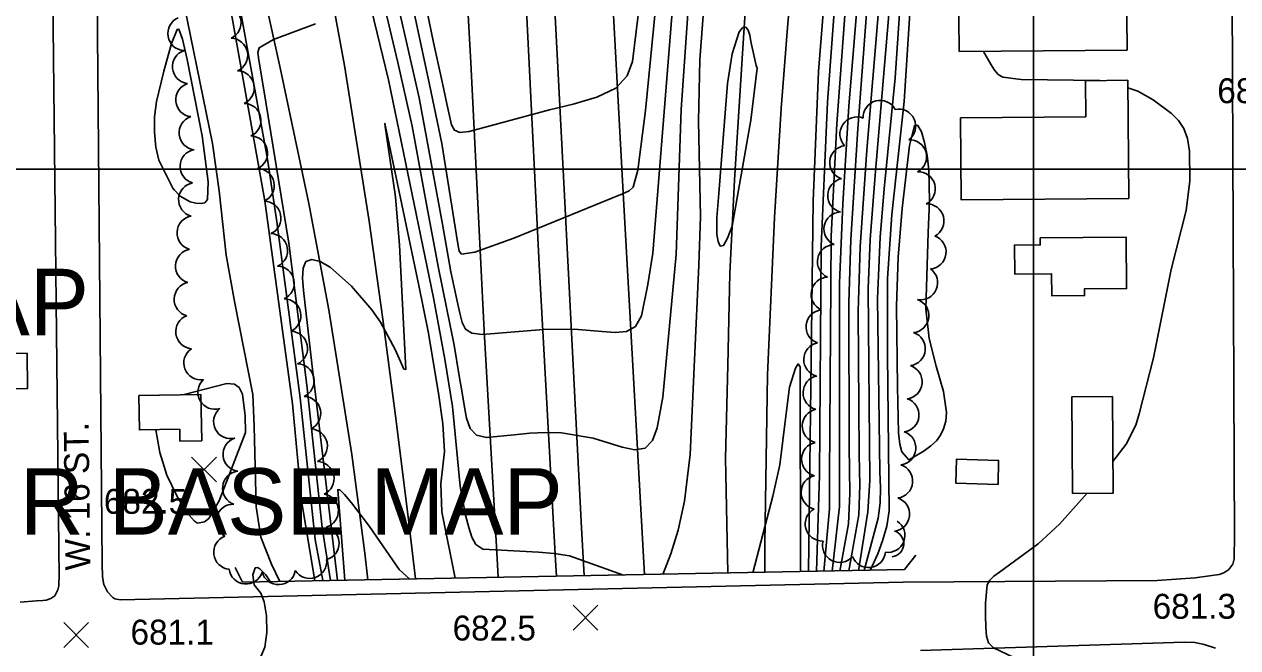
# Model space of a CAD drawing. Extents: x 79600 to 91800, y 75600 to 84400.
# Drawn here: x 86092 to 86823, y 78712 to 79087 of the extents above; entities that cross this region are included whole.
import ezdxf

# ---------------------------------------------------------------- set-up
doc = ezdxf.new("R2010")
doc.units = 0
for name, color, linetype in [('080-085$0$TI_BORDER', 7, 'Continuous'), ('080-085$0$TI_ORTHO_BM', 7, 'Continuous'), ('080-085$0$TI_ORTHO_CBM', 7, 'Continuous'), ('080-090$0$BLDG', 7, 'Continuous'), ('080-090$0$BRIDGE', 7, 'Continuous'), ('080-090$0$GRID', 7, 'Continuous'), ('080-090$0$INDEX', 7, 'Continuous'), ('080-090$0$INTER', 7, 'Continuous'), ('080-090$0$INTERSTATE', 7, 'Continuous'), ('080-090$0$ROAD', 7, 'Continuous'), ('080-090$0$ROAD-NAME', 7, 'Continuous'), ('080-090$0$SPOTMARK', 7, 'Continuous'), ('080-090$0$SPOTS', 7, 'Continuous'), ('080-090$0$TREES', 7, 'Continuous')]:
    doc.layers.add(name, color=color, linetype=linetype)

# ---------------------------------------------------------------- blocks, each defined once
blk = doc.blocks.new('080-090$0$SPOTS')
at = {"layer": '080-090$0$SPOTMARK'}
for p, q in [((-0.5, -0.5), (0.5, 0.5)), ((-0.5, 0.5), (0.5, -0.5))]:
    blk.add_line(p, q, dxfattribs=at)

msp = doc.modelspace()

# ---------------------------------------------------------------- linework, layer by layer
at = {"layer": '080-085$0$TI_BORDER'}
msp.add_lwpolyline([(79700, 80300), (86700, 80300), (86700, 75700), (79700, 75700)], close=True, dxfattribs=at)
at = {"layer": '080-090$0$BLDG'}
for points in [[(86655.25, 79070.71), (86756.42, 79071.59), (86756.07, 79112.06), (86654.89, 79111.18)], [(86731.56, 79031.43), (86731.37, 79053.21), (86756.8, 79053.43), (86757.42, 78982.31), (86656.59, 78981.44), (86656.16, 79030.78)], [(86704.1, 78958.66), (86704.13, 78954.42), (86688.63, 78954.28), (86688.79, 78936.8), (86710.99, 78936.99), (86711.11, 78923.76), (86730.79, 78923.93), (86730.75, 78927.89), (86756.12, 78928.11), (86755.85, 78959.11)], [(86094.11, 78889.17), (86057.05, 78888.61), (86057.37, 78867.46), (86094.43, 78868.02)], [(86161.4, 78863.73), (86161.71, 78843.04), (86186.07, 78843.41), (86186.17, 78836.37), (86199.23, 78836.57), (86198.81, 78864.29)], [(86747.6, 78863.14), (86748.1, 78805.05), (86723.6, 78804.83), (86723.09, 78862.93)], [(86678.72, 78810.25), (86653.33, 78810.91), (86653.7, 78825.37), (86679.1, 78824.71)]]:
    msp.add_lwpolyline(points, close=True, dxfattribs=at)
at = {"layer": '080-090$0$BRIDGE'}
for p, q in [((86622.49, 78759.11), (86629.26, 78767.59)), ((86219.38, 78760.18), (86223.82, 78751.39)), ((86223.82, 78751.39), (86622.49, 78759.11))]:
    msp.add_line(p, q, dxfattribs=at)
at = {"layer": '080-090$0$GRID'}
msp.add_line((90000, 79000), (85000, 79000), dxfattribs=at)
at = {"layer": '080-090$0$INDEX'}
for points in [[(86794.84, 80000), (86783.11, 79983.55), (86767.05, 79957.92), (86758.01, 79940.3), (86743.03, 79904.75), (86719.25, 79841.72), (86707.01, 79806.04), (86679.46, 79703.71), (86668.02, 79658.6), (86660.02, 79622.49), (86647.85, 79558.56), (86633.32, 79464.99), (86610.07, 79282.52), (86599.03, 79207.39), (86591.82, 79149.83), (86587.83, 79111.6), (86581.57, 79027.31), (86578.33, 78959.69), (86577.33, 78815.09), (86577.23, 78795.59), (86573.92, 78757.92)], [(86800.04, 79977.16), (86787.89, 79956.36), (86780.56, 79938.68), (86749.38, 79836.84), (86697.53, 79644.09), (86690.23, 79616.74), (86680.01, 79569.49), (86660.4, 79437.95), (86654.03, 79389.47), (86649.19, 79341.29), (86646.22, 79282.72), (86644.79, 79263.44), (86630.75, 79187.68), (86624.79, 79150.58), (86621.37, 79123.29), (86616.84, 79054.9), (86610.12, 78988.14), (86607.68, 78959.03), (86606.12, 78922.22), (86607.62, 78817.75), (86607.87, 78808.44), (86607.67, 78799.18), (86606.63, 78790.02), (86598.08, 78758.37)], [(86246.21, 78751.85), (86241.19, 78762.32), (86234.9, 78778.52), (86232.13, 78796.81), (86230.81, 78845.4), (86230.04, 78864.39), (86219.18, 78919.23), (86213.99, 78948.14), (86209.79, 78986.84), (86205.66, 79015.43), (86184.94, 79117.68), (86169.63, 79202.98), (86155.24, 79295.88), (86134.2, 79408.83), (86127.12, 79446.68), (86118.5, 79483.87), (86106.7, 79530.75)], [(86267.44, 78752.25), (86259.35, 78800.5), (86253.88, 78858.84), (86237.2, 78980.86), (86199.89, 79190.16)], [(86296.31, 79191.91), (86330.19, 79042.93), (86344.29, 78966.77), (86349.32, 78938.16), (86351.25, 78929), (86353.14, 78920.53), (86354.76, 78913.26), (86356.12, 78907.6), (86358.11, 78903.61), (86361.86, 78901.25), (86368.14, 78900.43), (86404.96, 78903.4), (86423.45, 78903.74), (86440.43, 78902.37), (86448.23, 78901.67), (86455.09, 78902.21), (86460.45, 78905.29), (86463.99, 78911.78), (86467.82, 78930.53), (86470.84, 78949.48), (86486.93, 79149.75)]]:
    msp.add_lwpolyline(points, dxfattribs=at)
at = {"layer": '080-090$0$INTER'}
for points in [[(86785.85, 80000), (86772.33, 79981.48), (86762.36, 79966.03), (86752.85, 79949.06), (86736.17, 79914.45), (86721.14, 79879.02), (86703.54, 79833.6), (86690.47, 79796.23), (86666.03, 79704.25), (86657.03, 79668.46), (86645.97, 79613.62), (86635.58, 79556.42), (86620.34, 79460.97), (86591.99, 79260.49), (86584.81, 79205.6), (86575.71, 79121.74), (86570.67, 79058.78), (86567.36, 78980.62), (86564.6, 78757.75)], [(86790.46, 80000), (86775.69, 79979.74), (86761.13, 79955.97), (86748.7, 79930.22), (86733.83, 79895.73), (86716.45, 79850.83), (86703.05, 79813.95), (86694.22, 79785.97), (86672.55, 79703.18), (86663.19, 79666.37), (86654.84, 79627.73), (86642.47, 79561.99), (86627.36, 79466.66), (86594.98, 79229.34), (86587.9, 79172.84), (86581.76, 79116.56), (86575.97, 79040.28), (86572.27, 78953.52), (86571.26, 78815.88), (86569.34, 78757.84)], [(86799.91, 80000), (86785.98, 79981.15), (86775.44, 79964.65), (86765.95, 79947.11), (86754.38, 79919.95), (86734.14, 79865.32), (86721.46, 79829.9), (86710.03, 79793.54), (86685.27, 79700), (86671.18, 79644.22), (86661.04, 79596.02), (86653.77, 79557.73), (86636.48, 79444.47), (86626.68, 79370.64), (86616.7, 79277.49), (86605.13, 79200.38), (86597.49, 79142.66), (86588.9, 79037.78), (86585.29, 78979.02), (86583.25, 78931.49), (86583.34, 78816.29), (86583.31, 78796.92), (86578.77, 78758.01)], [(86800.15, 79994.9), (86788.5, 79978.41), (86778.62, 79962.52), (86769.75, 79945.46), (86759.1, 79918.69), (86736.43, 79854.58), (86724.07, 79817.83), (86693.17, 79704.08), (86676.27, 79637.8), (86667.84, 79599.72), (86658.8, 79551.99), (86641.97, 79439.63), (86631.24, 79355.51), (86623.29, 79271.4), (86611.3, 79195.53), (86604.7, 79147.77), (86600.71, 79109.86), (86594.35, 79024.24), (86590.04, 78957.56), (86588.82, 78919.68), (86589.16, 78833.11), (86589.55, 78805.07), (86588.64, 78786.49), (86583.52, 78758.1)], [(86800.26, 79988.38), (86795.22, 79981.63), (86785.33, 79966.12), (86776.26, 79949.31), (86768.82, 79931.84), (86738.24, 79841.66), (86726.87, 79804.96), (86684.62, 79644.95), (86677.8, 79617.25), (86669.85, 79579.4), (86663.15, 79541.36), (86646.41, 79427.52), (86639.13, 79368.82), (86632.03, 79284.84), (86628.74, 79256.41), (86617.22, 79190.07), (86610.73, 79143.3), (86599.75, 79011.42), (86595.65, 78953.14), (86594.59, 78914.32), (86595.17, 78828.2), (86595.55, 78809.8), (86594.84, 78791.85), (86588.84, 78758.2)], [(86793.29, 79971.93), (86783.86, 79955.66), (86776.17, 79938.96), (86747.15, 79849.66), (86733.2, 79803.8), (86691.64, 79646.94), (86684.36, 79618.64), (86676.24, 79580.77), (86669.35, 79542.81), (86653.04, 79430.48), (86645.76, 79371.29), (86639.19, 79283.96), (86636.06, 79255.3), (86624.37, 79190.92), (86617.24, 79142.72), (86604.75, 78996.34), (86601.69, 78957.57), (86600.49, 78928.14), (86601.53, 78812.54), (86600.4, 78793.66), (86594.77, 78758.31)], [(86476.85, 78756.13), (86481.69, 78768.42), (86486.16, 78782.8), (86489.97, 78800.08), (86493.43, 78828.29), (86498.63, 78942.09), (86499.6, 78971.48), (86498.29, 79028.94), (86499.11, 79065.82), (86506.03, 79156.31), (86517.48, 79335.46), (86519.47, 79381.53), (86523.84, 79574.39)], [(86222.24, 79539.9), (86232.45, 79482.79), (86256.28, 79378.8), (86288.37, 79259.35), (86300.95, 79211.61), (86310.3, 79172.83), (86336.33, 79050.86), (86343.87, 79015.36), (86353.5, 78954.99), (86354.33, 78950.7), (86355.75, 78948.71), (86363.75, 78949.92), (86387.13, 78958.44), (86446.27, 78982.58), (86452.52, 78985.13), (86456.59, 78987), (86458.99, 78989.19), (86461.93, 78999.38), (86466.52, 79035.2), (86476.51, 79137.68), (86489.91, 79307.72), (86493.54, 79364.18), (86500.29, 79544.81)], [(86601.82, 78758.44), (86606.26, 78768.56), (86609.2, 78776.31), (86611.75, 78785.2), (86613.25, 78794.45), (86612.12, 78888.51), (86612.21, 78934.2), (86614.77, 78972.7), (86622.11, 79040.64), (86626.39, 79106.48), (86629.16, 79133.73), (86634.65, 79171.25), (86645.73, 79225.91), (86650.7, 79252.87), (86652.94, 79270.83), (86654.19, 79318.36), (86658.04, 79367.8), (86663.46, 79416.58), (86679.61, 79530.52)], [(86290.01, 79179.19), (86317.24, 79064.13), (86325.93, 79025.89), (86334.85, 78977.71), (86341.78, 78940.43), (86351.23, 78893.98), (86354.32, 78875.55), (86355.82, 78866.48), (86357.23, 78857.9), (86358.66, 78850.17), (86360.84, 78843.94), (86364.66, 78839.9), (86370.72, 78838.45), (86387.48, 78839.99), (86396.82, 78841.02), (86406.36, 78841.53), (86415.97, 78841.25), (86434.86, 78837.99), (86452.49, 78832.62), (86460.12, 78831.01), (86466.28, 78832.03), (86470.62, 78836.72), (86473.5, 78844.22), (86476.98, 78862.71), (86484.94, 78948.69), (86487.87, 79035.84), (86506.62, 79304.04)], [(86311.89, 79206.47), (86338.91, 79076.1), (86342.93, 79057.18), (86344.97, 79047.86), (86346.87, 79039.23), (86348.42, 79031.98), (86349.63, 79026.67), (86351.36, 79023.37), (86354.67, 79022.06), (86360.33, 79022.6), (86408.66, 79035.71), (86422.91, 79039.07), (86437.07, 79043.23), (86448.54, 79048.79), (86455.42, 79056.13), (86458.73, 79064.74), (86465.18, 79119.02)], [(86272.27, 78752.34), (86267.54, 78777.01), (86258.55, 78862.36), (86244.46, 78968.19), (86238.88, 79005.93), (86217.32, 79124.06)], [(86296.24, 79117.56), (86311.72, 79053.67), (86338.73, 78922.47), (86345.6, 78885.62), (86350.24, 78857.08), (86354.83, 78809.28), (86358.14, 78791.68), (86360.02, 78784.3), (86361.83, 78778.42), (86364.34, 78774.11), (86368.52, 78771.33), (86401.97, 78769.41), (86411.39, 78768.77), (86420.77, 78767.3), (86453.19, 78755.69)], [(86276.73, 78752.42), (86271.72, 78784.31), (86262.49, 78869.95), (86251.64, 78955.51), (86236.35, 79050.2), (86233.67, 79065.65), (86233.14, 79070.14), (86233.94, 79073.01), (86242.53, 79077.89), (86267.84, 79087.49)], [(86669.96, 79070.84), (86674.55, 79062.77), (86676.66, 79059.54), (86678.82, 79057), (86681.68, 79055.23), (86692.58, 79053.82), (86740.11, 79053.28)], [(86756.84, 79048.89), (86762.97, 79046.87), (86772.21, 79041.66), (86783.16, 79033.46), (86787.44, 79029.2), (86790.62, 79024.42), (86792.78, 79018.45), (86793.98, 79010.83), (86794.13, 78992.87), (86792.04, 78975), (86782.92, 78939.57), (86772.27, 78886.48), (86763.75, 78852.65), (86761.61, 78845.97), (86755.84, 78834.46), (86747.94, 78824.01)], [(86281.03, 78752.5), (86265.62, 78883.06), (86260.51, 78927.03), (86260, 78934.46), (86260.31, 78940.48), (86262.02, 78944.37), (86265.55, 78945.6), (86270.56, 78944.35), (86276.5, 78940.98), (86289.41, 78929.55), (86301.64, 78915.35), (86306.99, 78907.83), (86315.74, 78891.47), (86318.9, 78884.17), (86321.05, 78879.7), (86322.11, 78879.36), (86318.27, 78954.15), (86315.91, 78983.22), (86310.61, 79020.29), (86309.76, 79025.72), (86309.59, 79027.54), (86330.07, 78929.94), (86335.7, 78902.32), (86341.9, 78865.15), (86344.42, 78846.67), (86345.43, 78830.09), (86343.33, 78810.54), (86343.84, 78793.73), (86351.79, 78753.81)], [(86531.1, 78757.13), (86543.22, 78803.11), (86547.42, 78822.1), (86550.94, 78851.28), (86553.14, 78868.75), (86556.79, 78880.12), (86558.36, 78882.76), (86559.59, 78881.08), (86559.82, 78757.66)], [(86225.68, 78841.43), (86225.34, 78851.54), (86223.75, 78864.49), (86221.9, 78868.55), (86218.91, 78870.55), (86214.38, 78870.92), (86187.84, 78864.13)], [(86171.69, 78843.19), (86174.09, 78829.46), (86178.34, 78815.8), (86184.41, 78803.01), (86190.38, 78793.45), (86194.97, 78788.1), (86196.81, 78787.02), (86200.96, 78787.65), (86203.54, 78789.83), (86209.67, 78800.4), (86225.68, 78841.43)], [(86324.59, 78753.31), (86318.1, 78759.02), (86300.35, 78784.98), (86289.5, 78799.17), (86285.21, 78804.17), (86282.48, 78806.95), (86281.13, 78807), (86285.49, 78752.58)], [(86732.39, 78804.91), (86715.82, 78786.32), (86702.86, 78774.48), (86679.65, 78757.52), (86676.19, 78755), (86673.75, 78752.67), (86672.19, 78749.73), (86671.09, 78738.76), (86671.17, 78731.27), (86671.4, 78724.29), (86671.76, 78718.95), (86672.97, 78714.99), (86675.94, 78711.81), (86688.33, 78706.18), (86719.18, 78696.45)], [(86240.53, 78751.75), (86237.95, 78755.77), (86234.3, 78759.39), (86232.75, 78760.23), (86231.52, 78760.02), (86229.98, 78755.88), (86230.77, 78749.73), (86234.85, 78744.81), (86236.92, 78739.66), (86238.18, 78731.07), (86238.37, 78721.05), (86237.33, 78712.35), (86234.98, 78707.01), (86231.67, 78704.34), (86206.38, 78695.78), (86198.65, 78692.75), (86191.64, 78688.59), (86186.34, 78683.19), (86178.82, 78669.47)]]:
    msp.add_lwpolyline(points, dxfattribs=at)
for points in [[(86182.7, 78987.43), (86186.31, 78983.72), (86192.32, 78980.34), (86195.7, 78979.5), (86198.75, 78979.27), (86201.1, 78979.77), (86202.65, 78981.66), (86203.19, 78992.32), (86199.55, 79020.05), (86190.59, 79065.9), (86187.76, 79078.17), (86185.55, 79084.13), (86184.42, 79084.06), (86181.14, 79075.59), (86176.53, 79058.89), (86172.1, 79040.76), (86170.86, 79031.52), (86170.73, 79022.17), (86171.61, 79013.22), (86173.34, 79005.3), (86181.87, 78988.44)], [(86533.18, 79062.43), (86529.84, 79076.86), (86529.24, 79080.62), (86528.35, 79083.61), (86526.93, 79085.38), (86525.08, 79085.29), (86522.94, 79082.65), (86518.59, 79069.36), (86515.79, 79051.57), (86510.7, 78985.35), (86509.43, 78970.84), (86509.43, 78960.6), (86510.16, 78956.34), (86511.46, 78953.69), (86513.4, 78954.05), (86515.93, 78958.34), (86518.61, 78965.59), (86529.83, 79029.4), (86533.61, 79060.79)], [(86626.8, 78826.05), (86634.27, 78830.54), (86638.36, 78833.49), (86641.67, 78836.56), (86644.16, 78839.9), (86645.98, 78843.73), (86647.21, 78848.23), (86647.72, 78853.46), (86645.9, 78866.2), (86641.44, 78881.4), (86637.28, 78897.99), (86635.16, 78915.91), (86636.67, 78961.88), (86637.55, 78980.73), (86637.02, 78999.48), (86636, 79008.23), (86634.49, 79016.06), (86632.56, 79022.43), (86630.46, 79026.26), (86628.46, 79026.33), (86625.43, 79014.21), (86621.07, 78976.21), (86618.51, 78947), (86617.67, 78917.52), (86618.2, 78868.96), (86618.77, 78841.34), (86619.5, 78834.42), (86620.72, 78829.78), (86624.94, 78825.05)]]:
    msp.add_lwpolyline(points, close=True, dxfattribs=at)
at = {"layer": '080-090$0$INTERSTATE'}
for p, q in [((86417.59, 78987.84), (86396.6, 79388.93)), ((86524.78, 79069.56), (86545.19, 79370.31)), ((86213.41, 79209.92), (86246.58, 79060.96)), ((86564.24, 79213.53), (86551.88, 79085.21)), ((86354.08, 79199.03), (86361.29, 79064.18)), ((86442.78, 79176.62), (86452.78, 78989.24)), ((86285.24, 79062.44), (86271.05, 79139.52)), ((86394.03, 79113.12), (86402.49, 78942.65)), ((86551.88, 79085.21), (86548.09, 79036.52)), ((86520.15, 78993.61), (86524.78, 79069.56)), ((86300.14, 78968.74), (86285.24, 79062.44)), ((86361.29, 79064.18), (86369.33, 78902.73)), ((86246.58, 79060.96), (86263.74, 78979.27)), ((86548.09, 79036.52), (86544.17, 78970.94)), ((86452.78, 78989.24), (86465.87, 78756.08)), ((86517.21, 78937.15), (86520.15, 78993.61)), ((86427.89, 78784.12), (86417.59, 78987.84)), ((86263.74, 78979.27), (86275.77, 78915.38)), ((86308.37, 78909.62), (86300.14, 78968.74)), ((86544.17, 78970.94), (86539.95, 78876.15)), ((86402.49, 78942.65), (86412.35, 78764.55)), ((86515.94, 78881.92), (86517.21, 78937.15)), ((86275.77, 78915.38), (86289.67, 78828.34)), ((86315.92, 78851.62), (86308.37, 78909.62)), ((86369.33, 78902.73), (86376.98, 78769.25)), ((86514.67, 78825.99), (86515.94, 78881.92)), ((86539.95, 78876.15), (86538.25, 78774.67)), ((86323.58, 78790.84), (86315.92, 78851.62)), ((86289.67, 78828.34), (86297.48, 78768.95)), ((86516.06, 78757.05), (86514.67, 78825.99)), ((86328.04, 78753.41), (86323.58, 78790.84)), ((86429.5, 78755.37), (86427.89, 78784.12)), ((86538.25, 78774.67), (86538.39, 78757.48)), ((86297.48, 78768.95), (86299.31, 78752.85)), ((86376.98, 78769.25), (86377.73, 78754.37)), ((86412.35, 78764.55), (86412.82, 78755.05))]:
    msp.add_line(p, q, dxfattribs=at)
at = {"layer": '080-090$0$ROAD'}
for p, q in [((86107.95, 79258.9), (86113.35, 78754.19)), ((86139.38, 78762.52), (86135.81, 79161.12)), ((86819.49, 79143.28), (86821.06, 78776.83)), ((86821.06, 78776.83), (86820.93, 78768.38)), ((86820.89, 78765.48), (86820.15, 78762.3)), ((86820.93, 78768.38), (86820.89, 78765.48)), ((86139.53, 78754.62), (86139.38, 78762.52)), ((86806.05, 78755.32), (86797.45, 78754.07)), ((86811.88, 78756.06), (86806.05, 78755.32)), ((86814.67, 78756.99), (86811.88, 78756.06)), ((86817.6, 78759.02), (86814.67, 78756.99)), ((86820.15, 78762.3), (86817.6, 78759.02)), ((86113.27, 78749.21), (86112.68, 78746.72)), ((86113.31, 78751.15), (86113.27, 78749.21)), ((86113.35, 78754.19), (86113.31, 78751.15)), ((86140.29, 78750.04), (86139.53, 78754.62)), ((86142.44, 78745.57), (86140.29, 78750.04)), ((86621.68, 78751.51), (86150.12, 78740.75)), ((86774.57, 78752.34), (86621.68, 78751.51)), ((86797.45, 78754.07), (86774.57, 78752.34)), ((86105.53, 78740.6), (86103.58, 78740.35)), ((86108.45, 78741.53), (86105.53, 78740.6)), ((86110.83, 78743.29), (86108.45, 78741.53)), ((86112.68, 78746.72), (86110.83, 78743.29)), ((86145.71, 78742.2), (86142.44, 78745.57)), ((86146.95, 78741.49), (86145.71, 78742.2)), ((86150.12, 78740.75), (86146.95, 78741.49)), ((86099.7, 78740.14), (86089.86, 78739.32)), ((86103.58, 78740.35), (86099.7, 78740.14)), ((86791.04, 78715.25), (86632.12, 78710.35)), ((86797.26, 78715.02), (86791.04, 78715.25)), ((86802.92, 78713.82), (86797.26, 78715.02)), ((86809.68, 78711.78), (86802.92, 78713.82))]:
    msp.add_line(p, q, dxfattribs=at)
at = {"layer": '080-090$0$TREES'}
for centre, radius, start, end in [((86212.69, 79088.1), 10.25, 294.21764, 88.85687), ((86189.08, 79081.59), 10.25, 112.87035, 267.50958), ((86216.69, 79068.51), 10.25, 294.21764, 88.85687), ((86191.88, 79061.63), 10.25, 108.45316, 263.09239), ((86220.69, 79048.91), 10.25, 294.21764, 88.85687), ((86193.89, 79041.73), 10.25, 108.45316, 263.09239), ((86607.76, 79031.1), 10.25, 27.80878, 182.44801), ((86224.69, 79029.32), 10.25, 294.21764, 88.85687), ((86618.88, 79025.84), 10.25, 306.9354, 101.57463), ((86195.9, 79021.83), 10.25, 108.45316, 263.09239), ((86593.78, 79021.11), 10.25, 68.64443, 223.28366), ((86228.69, 79009.72), 10.25, 294.21764, 88.85687), ((86196.48, 79001.57), 10.25, 100.19458, 254.83382), ((86587.64, 79003.92), 10.25, 97.36271, 252.00194), ((86625.48, 79007.4), 10.25, 297.84557, 92.4848), ((86232.69, 78990.12), 10.25, 294.21764, 88.85687), ((86630.72, 78988.1), 10.25, 297.84557, 92.4848), ((86195.58, 78981.58), 10.25, 100.00524, 254.64448), ((86586.41, 78984.11), 10.25, 100.91425, 255.55349), ((86236.69, 78970.53), 10.25, 294.21764, 88.85687), ((86635.95, 78968.8), 10.25, 297.84557, 92.4848), ((86194.65, 78961.6), 10.25, 100.00524, 254.64448), ((86584.17, 78963.94), 10.25, 91.76102, 246.40025), ((86240.69, 78950.93), 10.25, 294.21764, 88.85687), ((86580.27, 78944.3), 10.25, 91.17295, 245.81219), ((86637.18, 78950.12), 10.25, 275.06685, 69.70609), ((86193.71, 78941.63), 10.25, 100.00524, 254.64448), ((86244.7, 78931.34), 10.25, 294.21764, 88.85687), ((86632.12, 78931.58), 10.25, 259.74545, 54.38468), ((86192.91, 78921.67), 10.25, 100.75893, 255.39816), ((86576.4, 78924.7), 10.25, 91.81899, 246.45822), ((86248.7, 78911.74), 10.25, 294.21764, 88.85687), ((86626.86, 78911.83), 10.25, 275.81716, 70.45639), ((86193.9, 78902.15), 10.25, 110.41989, 265.05912), ((86573.37, 78905.11), 10.25, 95.95173, 250.59096), ((86252.7, 78892.14), 10.25, 294.21764, 88.85687), ((86624.71, 78891.9), 10.25, 277.21182, 71.85106), ((86571.99, 78885.4), 10.25, 101.42985, 256.06908), ((86198.73, 78883.42), 10.25, 123.85143, 278.49066), ((86256.7, 78872.55), 10.25, 294.21764, 88.85687), ((86622.8, 78871.99), 10.25, 277.21182, 71.85106), ((86207.15, 78865.71), 10.25, 132.31536, 286.9546), ((86571.56, 78865.4), 10.25, 101.42985, 256.06908), ((86260.7, 78852.95), 10.25, 294.21764, 88.85687), ((86620.9, 78852.08), 10.25, 277.21182, 71.85106), ((86216.69, 78848.02), 10.25, 129.7751, 284.41434), ((86571.12, 78845.4), 10.25, 101.42985, 256.06908), ((86264.7, 78833.36), 10.25, 294.21764, 88.85687), ((86222.35, 78828.33), 10.25, 107.62414, 262.26337), ((86618.99, 78832.17), 10.25, 277.21182, 71.85106), ((86570.68, 78825.41), 10.25, 101.42985, 256.06908), ((86268.7, 78813.76), 10.25, 294.21764, 88.85687), ((86617.09, 78812.26), 10.25, 277.21182, 71.85106), ((86222.06, 78807.98), 10.25, 96.13964, 250.77887), ((86570.4, 78805.45), 10.25, 102.3106, 256.94984), ((86271.3, 78794.29), 10.25, 286.35235, 80.99158), ((86615.18, 78792.35), 10.25, 277.21182, 71.85106), ((86218.13, 78788.07), 10.25, 86.8669, 241.50614), ((86572.9, 78786.41), 10.25, 118.01277, 272.65201), ((86272.14, 78774.77), 9.89, 283.43674, 78.07597), ((86612.41, 78779.58), 10.25, 261.75978, 56.39901), ((86216.71, 78769.41), 10.25, 109.774, 264.41323), ((86613.98, 78774.61), 7.97, 277.21182, 71.85106), ((86583.28, 78773.54), 10.25, 165.0969, 319.73614), ((86264.26, 78763.89), 10.25, 212.42538, 7.06462), ((86600.74, 78770.41), 10.25, 199.93633, 354.57556), ((86225.87, 78760.58), 10.25, 187.69825, 342.33748), ((86245.52, 78760.18), 10.25, 195.31253, 349.95177)]:
    msp.add_arc(centre, radius, start, end, dxfattribs=at)

# ---------------------------------------------------------------- block references
at = {"layer": '080-090$0$SPOTMARK', "xscale": 15, "yscale": 15}
for p in [(86200.58, 78819.21), (86430.36, 78730.11), (86123.66, 78719.68)]:
    msp.add_blockref('080-090$0$SPOTS', p, dxfattribs=at)

# ---------------------------------------------------------------- texts
at = {"layer": '080-085$0$TI_ORTHO_BM'}
msp.add_text('ORTHOPHOTO  BASE  MAP', height=40, dxfattribs=at).set_placement((85430, 78900))
at = {"layer": '080-085$0$TI_ORTHO_CBM'}
msp.add_text('ORTHOPHOTO / CONTOUR BASE MAP', height=40, dxfattribs=at).set_placement((85430, 78780))
at = {"layer": '080-090$0$ROAD-NAME'}
msp.add_text('W. 16 ST.', height=15, rotation=90.65918, dxfattribs=at).set_placement((86132.17, 78758.6))
at = {"layer": '080-090$0$SPOTS'}
for s, p in [('681.3', (86810.72, 79039.67)), ('682.5', (86140.32, 78792.56)), ('681.3', (86771.82, 78729.41)), ('681.1', (86156.39, 78713.85)), ('682.5', (86350.3, 78716.32))]:
    msp.add_text(s, height=15, dxfattribs=at).set_placement(p)

doc.saveas('drawing.dxf')
